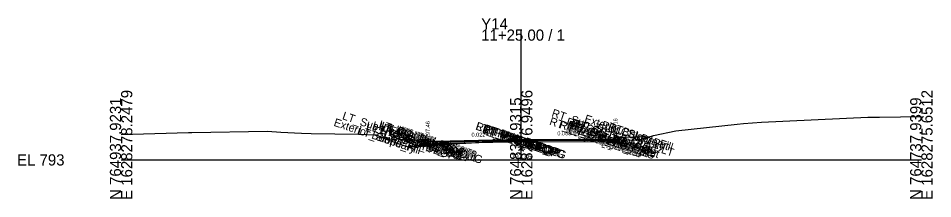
# Model space of a CAD drawing. Extents: x -26 to 1403, y -10 to 4517.
# Drawn here: x -25.7 to 202.8, y 2490.3 to 2535.4 of the extents above; entities that cross this region are included whole.
import ezdxf

# ---------------------------------------------------------------- set-up
doc = ezdxf.new("R2010")
doc.units = 0
for name, color, linetype in [('Default', 7, 'Continuous'), ('Exist CMT Pavement', 7, 'Continuous'), ('Exist Cross Section Cell', 7, 'Continuous'), ('Exist XS Center Line Elevation Label', 7, 'Continuous'), ('Exist XS Ground Line', 7, 'Continuous'), ('Prop CMT Conc Surface', 7, 'Continuous'), ('Prop CMT Concrete Structures', 7, 'Continuous'), ('Prop CMT Pvmt Course 1', 7, 'Continuous'), ('Prop CMT Pvmt Course 1 CG', 7, 'Continuous'), ('Prop CMT Pvmt Course 1 Wedge', 7, 'Continuous'), ('Prop CMT Pvmt Course 2', 7, 'Continuous'), ('Prop CMT Pvmt Course 2 Wedge', 7, 'Continuous'), ('Prop CMT Pvmt Course 3', 7, 'Continuous'), ('Prop CMT Pvmt Course 3 Wedge', 7, 'Continuous'), ('Prop CMT Pvmt Surface', 7, 'Continuous'), ('Prop CMT Pvmt Wedge Surface 1', 7, 'Continuous'), ('Prop CMT Pvmt Wedge Surface 2', 7, 'Continuous'), ('Prop CMT Pvmt Wedge Surface 3', 7, 'Continuous'), ('Prop CMT Slope Grass', 7, 'Continuous'), ('Prop CMT Subgrade Earthwork', 7, 'Continuous'), ('Prop XS Hydro Elevations', 7, 'Continuous'), ('Prop XS SE Text', 7, 'Continuous'), ('Scratch_Level_0', 7, 'Continuous')]:
    doc.layers.add(name, color=color, linetype=linetype)

msp = doc.modelspace()

# ---------------------------------------------------------------- linework, layer by layer
at = {"layer": 'Exist CMT Pavement'}
for points in [[(100, 2504.85), (78.79, 2503.75)], [(100, 2504.85), (78.83, 2503.75)], [(100, 2504.85), (121.67, 2505)], [(100, 2504.85), (121.55, 2505)]]:
    msp.add_lwpolyline(points, dxfattribs=at)
at = {"layer": 'Exist Cross Section Cell'}
for p, q in [((100, 2500), (100, 2532.59)), ((0, 2500), (100, 2500)), ((100, 2500), (200, 2500))]:
    msp.add_line(p, q, dxfattribs=at)
at = {"layer": 'Exist XS Ground Line'}
msp.add_lwpolyline([(0, 2506.39), (16.82, 2506.82), (17.67, 2506.83), (36.63, 2507.21), (39.94, 2506.9), (45.07, 2506.67), (47.53, 2506.63), (59.36, 2506.45), (63.75, 2506.24), (66.38, 2505.13), (70.95, 2503.54), (71.78, 2503.26), (76.73, 2503.83), (78.87, 2503.75), (96.27, 2504.8), (97.05, 2504.84), (97.94, 2504.84), (100, 2504.86), (102.68, 2504.88), (119.79, 2504.99), (121.96, 2505), (122.73, 2505), (129.3, 2504.9), (133.03, 2506.06), (138.66, 2507.28), (153.97, 2508.95), (155.59, 2509.14), (160.05, 2509.4), (186.6, 2510.66), (189.54, 2510.71), (200, 2510.86)], dxfattribs=at)
at = {"layer": 'Prop CMT Conc Surface'}
for points in [[(76.64, 2504.46), (76.64, 2504.96), (76.14, 2504.96)], [(121.55, 2505.22), (123.55, 2505.16)], [(123.55, 2505.16), (123.55, 2505.66), (124.05, 2505.66)], [(78.64, 2504.58), (76.64, 2504.46)]]:
    msp.add_lwpolyline(points, dxfattribs=at)
at = {"layer": 'Prop CMT Concrete Structures'}
for points in [[(78.64, 2504.58), (76.64, 2504.46), (76.64, 2504.96), (76.14, 2504.96)], [(76.14, 2504.96), (76.14, 2503.94), (78.64, 2504)], [(121.55, 2505.22), (123.55, 2505.16), (123.55, 2505.66), (124.05, 2505.66)], [(124.05, 2505.66), (124.05, 2504.66), (121.55, 2504.64)], [(121.55, 2504.64), (121.55, 2505.22)], [(78.64, 2504), (78.64, 2504.58)]]:
    msp.add_lwpolyline(points, dxfattribs=at)
at = {"layer": 'Prop CMT Pvmt Course 1'}
for points in [[(100, 2505.06), (78.64, 2504.58)], [(78.83, 2504.46), (100, 2504.94)], [(100, 2505.06), (121.55, 2505.22)], [(121.55, 2505.1), (100, 2504.94)], [(100, 2504.81), (100, 2505.06)], [(100, 2504.81), (100, 2505.06)], [(100, 2504.94), (100, 2504.81), (100, 2504.81)], [(100, 2504.94), (100, 2504.81), (100, 2504.81)], [(121.55, 2505.22), (121.55, 2504.97), (121.55, 2504.97), (121.55, 2505.1)], [(78.64, 2504.58), (78.64, 2504.33)], [(78.64, 2504.33), (78.83, 2504.33)], [(78.83, 2504.33), (78.83, 2504.46)]]:
    msp.add_lwpolyline(points, dxfattribs=at)
at = {"layer": 'Prop CMT Pvmt Course 1 CG'}
for points in [[(78.64, 2504), (75.64, 2503.93), (75.3, 2503.59)], [(75.3, 2503.59), (78.64, 2503.66)], [(78.64, 2503.66), (78.64, 2504)], [(121.55, 2504.64), (124.55, 2504.66), (124.88, 2504.33)], [(121.55, 2504.31), (121.55, 2504.64)], [(124.88, 2504.33), (121.55, 2504.31)]]:
    msp.add_lwpolyline(points, dxfattribs=at)
at = {"layer": 'Prop CMT Pvmt Course 1 Wedge'}
for points in [[(100, 2504.94), (78.83, 2504.46)], [(100, 2504.94), (121.55, 2505.1)]]:
    msp.add_lwpolyline(points, dxfattribs=at)
at = {"layer": 'Prop CMT Pvmt Course 2'}
for points in [[(121.55, 2504.64), (121.55, 2504.64), (121.55, 2504.97), (121.55, 2504.97)], [(121.55, 2504.97), (121.55, 2504.64)], [(78.83, 2504.33), (78.64, 2504.33)], [(78.64, 2504.33), (78.64, 2504)], [(78.64, 2504), (78.83, 2504)], [(78.83, 2504), (78.83, 2504.33)]]:
    msp.add_lwpolyline(points, dxfattribs=at)
at = {"layer": 'Prop CMT Pvmt Course 2 Wedge'}
for points in [[(100, 2504.81), (78.83, 2504.33)], [(100, 2504.81), (121.55, 2504.97)]]:
    msp.add_lwpolyline(points, dxfattribs=at)
at = {"layer": 'Prop CMT Pvmt Course 3'}
for points in [[(78.83, 2504), (78.64, 2504)], [(78.64, 2504), (78.64, 2503.66)], [(78.64, 2503.66), (78.83, 2503.67)], [(78.83, 2503.67), (78.83, 2504)], [(121.55, 2504.64), (121.55, 2504.64), (121.55, 2504.31), (121.55, 2504.31)], [(121.55, 2504.31), (121.55, 2504.64)]]:
    msp.add_lwpolyline(points, dxfattribs=at)
at = {"layer": 'Prop CMT Pvmt Course 3 Wedge'}
for points in [[(100, 2504.48), (78.83, 2504)], [(100, 2504.48), (121.55, 2504.64)]]:
    msp.add_lwpolyline(points, dxfattribs=at)
at = {"layer": 'Prop CMT Pvmt Surface'}
for points in [[(100, 2505.06), (78.64, 2504.58)], [(100, 2505.06), (121.55, 2505.22)]]:
    msp.add_lwpolyline(points, dxfattribs=at)
at = {"layer": 'Prop CMT Pvmt Wedge Surface 1'}
for points in [[(100, 2504.94), (78.83, 2504.46)], [(100, 2504.94), (121.55, 2505.1)], [(121.55, 2504.97), (121.55, 2505.22)], [(121.55, 2505.1), (121.55, 2504.97), (121.55, 2504.97)], [(78.64, 2504.33), (78.64, 2504.58)], [(78.83, 2504.33), (78.64, 2504.33)], [(78.83, 2504.46), (78.83, 2504.33)]]:
    msp.add_lwpolyline(points, dxfattribs=at)
at = {"layer": 'Prop CMT Pvmt Wedge Surface 2'}
for points in [[(100, 2504.81), (78.64, 2504.33)], [(100, 2504.81), (121.55, 2504.97)], [(121.55, 2504.97), (121.55, 2505.22)], [(78.64, 2504.33), (78.64, 2504.58)]]:
    msp.add_lwpolyline(points, dxfattribs=at)
at = {"layer": 'Prop CMT Pvmt Wedge Surface 3'}
for points in [[(121.55, 2504.64), (121.55, 2505.22)], [(78.64, 2504), (78.64, 2504.58)], [(100, 2504.48), (78.64, 2504)], [(100, 2504.48), (121.55, 2504.64)]]:
    msp.add_lwpolyline(points, dxfattribs=at)
at = {"layer": 'Prop CMT Slope Grass'}
for points in [[(76.14, 2504.96), (66.34, 2505.15)], [(124.05, 2505.66), (132.27, 2505.82)]]:
    msp.add_lwpolyline(points, dxfattribs=at)
at = {"layer": 'Prop CMT Subgrade Earthwork'}
for points in [[(78.64, 2503.66), (75.3, 2503.59), (73.89, 2505)], [(121.55, 2504.31), (121.54, 2505)], [(121.55, 2504.31), (124.88, 2504.33), (126.25, 2505.7)], [(78.83, 2503.67), (78.64, 2503.66)], [(78.83, 2503.67), (78.84, 2503.75)], [(121.55, 2504.31), (121.55, 2504.31)]]:
    msp.add_lwpolyline(points, dxfattribs=at)

# ---------------------------------------------------------------- texts
at = {"layer": 'Default'}
msp.add_text('-', height=0.0001, dxfattribs=at).set_placement((0, 2500))
at = {"layer": 'Exist Cross Section Cell'}
for s, p in [('Y14', (90, 2532.59)), ('11+25.00 / 1', (90, 2529.79)), ('EL 793', (-26, 2498.6))]:
    msp.add_text(s, height=2.8, dxfattribs=at).set_placement(p)
for s, p in [('E 1628278.2479', (2.8, 2490)), ('E 1628276.9496', (102.8, 2490)), ('E 1628275.6512', (202.8, 2490)), ('N 764937.9231', (0, 2490)), ('N 764837.9315', (100, 2490)), ('N 764737.9399', (200, 2490))]:
    msp.add_text(s, height=2.8, rotation=90, dxfattribs=at).set_placement(p)
at = {"layer": 'Exist XS Center Line Elevation Label'}
msp.add_text('797.86', height=1.2, dxfattribs=at).set_placement((97.54, 2500.26))
at = {"layer": 'Prop XS Hydro Elevations'}
for s, p in [('797.46', (77.14, 2505.46)), ('798.16', (124.05, 2506.16))]:
    msp.add_text(s, height=1, rotation=90, dxfattribs=at).set_placement(p)
at = {"layer": 'Prop XS SE Text'}
for s, rotation, p in [('0.008', 0.43, (109.03, 2506.13)), ('0.022', 1.2885, (87.59, 2505.78))]:
    msp.add_text(s, height=1, rotation=rotation, dxfattribs=at).set_placement(p)
at = {"layer": 'Scratch_Level_0'}
for s, p in [('LT_Sub_Trench_Out_DLT', (55.13, 2510.2)), ('RT_Sub_Trench_Out_DLT', (107.45, 2510.91)), ('Exterior Boundary', (52.98, 2508.56)), ('LT_CG_Top_Face', (64.23, 2508.04)), ('LT_PV_Sub_Tie_Out', (64.24, 2507.56)), ('LT_CG_Top_BOC', (64.71, 2507.71)), ('RT_PV_IEEOP_EG', (88.43, 2507.65)), ('LT_PV_IEEOP_EG', (88.48, 2507.63)), ('RT_PV_Sub_Tie_Out', (106.89, 2508.83)), ('RT_PV_OEEOP_EG', (109.37, 2508.01)), ('RT_CG_Top_Face', (111.1, 2508.75)), ('RT_CG1_Shelf_Out', (111.43, 2507.98)), ('RT_CG_Top_Gut', (112.03, 2507.94)), ('RT_CG_Top_BOC', (112.57, 2508.43)), ('Exterior Boundary', (115.6, 2509.48)), ('RT_CSLP_Pnt', (119.87, 2507.94)), ('RT_Slope_Fill', (121.61, 2507.48)), ('LT_Slope_Fill', (59.03, 2506.54)), ('LT_CSLP_Pnt', (61, 2507.22)), ('LT_CG1_Shelf_Out', (62.56, 2507.23)), ('LT_CG_Bot_BOC', (64.74, 2506.69)), ('LT_CG_Top_Gut', (65.16, 2507.23)), ('LT_Sub_OEOP', (65.6, 2505.77)), ('LT_PV_OEEOP_EG', (66.69, 2506.74)), ('LT_Sub_OEEOP', (68.28, 2506.13)), ('LT_PV2_OEEOP', (68.37, 2506.77)), ('LT_PV3_OEEOP', (68.37, 2506.43)), ('LT_CG_Bot_IE', (68.75, 2506.24)), ('LT_PV1_OEEOP', (68.9, 2506.71)), ('LT_Sub_OEOT', (68.91, 2505.85)), ('LT_PV2_OEOT', (69, 2506.49)), ('LT_PV3_OEOT', (69, 2506.16)), ('LT_PV1_OEOT', (69.54, 2506.56)), ('RT_PV2_IEEOP', (90.11, 2507.05)), ('RT_PV3_IEEOP', (90.11, 2506.72)), ('LT_PV2_IEEOP', (90.15, 2507.04)), ('LT_PV3_IEEOP', (90.15, 2506.71)), ('RT_PV1_IEEOP', (90.65, 2507)), ('LT_PV1_IEEOP', (90.69, 2506.98)), ('PV2_PGL', (93.9, 2505.79)), ('PV1_PGL', (94.44, 2505.86)), ('RT_Sub_OEEOP', (110.96, 2506.78)), ('RT_PV2_OEEOP', (111.04, 2507.42)), ('RT_PV3_OEEOP', (111.04, 2507.09)), ('RT_PV1_OEEOP', (111.58, 2507.37)), ('RT_CG_Bot_IE', (111.62, 2506.9)), ('RT_Sub_OEOT', (111.78, 2506.51)), ('RT_PV2_OEOT', (111.87, 2507.15)), ('RT_PV3_OEOT', (111.87, 2506.81)), ('RT_PV1_OEOT', (112.4, 2507.22)), ('RT_CG_Bot_BOC', (112.6, 2507.42)), ('RT_Sub_OEOP', (115.14, 2506.52))]:
    msp.add_text(s, height=2, rotation=341.5651, dxfattribs=at).set_placement(p)

doc.saveas('drawing.dxf')
